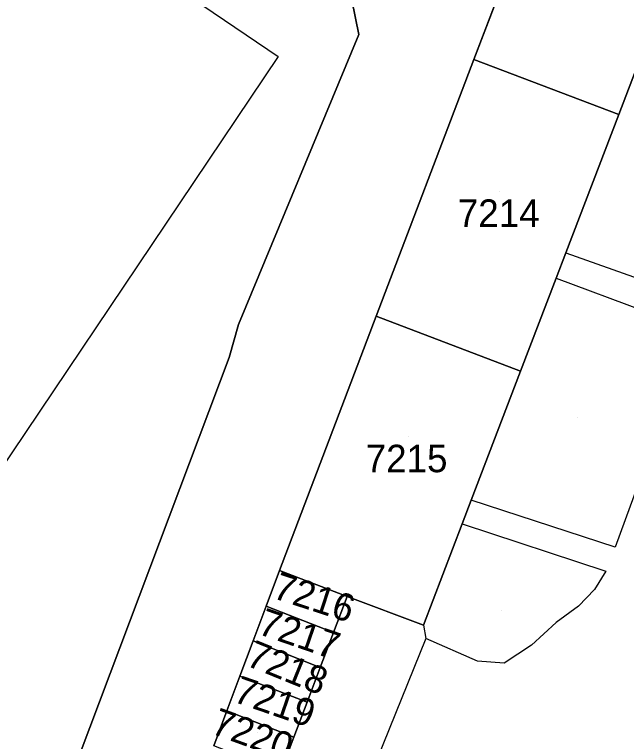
# Model space of a CAD drawing. Extents: x -266199 to -261993, y -1239047 to -1235108.
# Drawn here: x -263650.7 to -263606.2, y -1236545.7 to -1236492.8 of the extents above; entities that cross this region are included whole.
import ezdxf

# ---------------------------------------------------------------- set-up
doc = ezdxf.new("R2010")
doc.units = 0
for name, color, linetype in [('body_kn', 7, 'Continuous'), ('kladpar_druhypozemkov', 7, 'Continuous'), ('kladpar_hranice', 7, 'Continuous'), ('kladpar_parcelnecisla', 7, 'Continuous'), ('kladpar_plochy', 7, 'Continuous'), ('zappar_hrandruhpozemk', 7, 'Continuous')]:
    doc.layers.add(name, color=color, linetype=linetype)

msp = doc.modelspace()

# ---------------------------------------------------------------- linework, layer by layer
at = {"layer": 'body_kn'}
for p, q in [((-263625.65, -1236494.26), (-263625.65, -1236494.26)), ((-263631.52, -1236495.85), (-263631.52, -1236495.85)), ((-263631.52, -1236495.85), (-263631.52, -1236495.85)), ((-263617.27, -1236496.08), (-263617.27, -1236496.08)), ((-263617.27, -1236496.08), (-263617.27, -1236496.08)), ((-263606.72, -1236500.09), (-263606.72, -1236500.09)), ((-263606.72, -1236500.09), (-263606.72, -1236500.09)), ((-263610.57, -1236510.14), (-263610.57, -1236510.14)), ((-263610.57, -1236510.14), (-263610.57, -1236510.14)), ((-263611.28, -1236511.99), (-263611.28, -1236511.99)), ((-263611.28, -1236511.99), (-263611.28, -1236511.99)), ((-263624.38, -1236514.77), (-263624.38, -1236514.77)), ((-263624.38, -1236514.77), (-263624.38, -1236514.77)), ((-263634.41, -1236515.37), (-263634.41, -1236515.37)), ((-263635.09, -1236517.76), (-263635.09, -1236517.76)), ((-263613.87, -1236518.77), (-263613.87, -1236518.77)), ((-263613.87, -1236518.77), (-263613.87, -1236518.77)), ((-263617.46, -1236528.15), (-263617.46, -1236528.15)), ((-263618.12, -1236529.89), (-263618.12, -1236529.89)), ((-263618.12, -1236529.89), (-263618.12, -1236529.89)), ((-263607, -1236531.57), (-263607, -1236531.57)), ((-263631.43, -1236533.27), (-263631.43, -1236533.27)), ((-263631.43, -1236533.27), (-263631.43, -1236533.27)), ((-263607.67, -1236533.33), (-263607.67, -1236533.33)), ((-263626.49, -1236535.16), (-263626.49, -1236535.16)), ((-263608.5, -1236534.66), (-263608.5, -1236534.66)), ((-263632.4, -1236535.87), (-263632.4, -1236535.87)), ((-263632.4, -1236535.87), (-263632.4, -1236535.87)), ((-263609.66, -1236535.87), (-263609.66, -1236535.87)), ((-263620.94, -1236537.26), (-263620.94, -1236537.26)), ((-263620.94, -1236537.26), (-263620.94, -1236537.26)), ((-263611.28, -1236537.05), (-263611.28, -1236537.05)), ((-263627.48, -1236537.79), (-263627.48, -1236537.79)), ((-263620.77, -1236538.22), (-263620.77, -1236538.22)), ((-263620.77, -1236538.22), (-263620.77, -1236538.22)), ((-263633.34, -1236538.4), (-263633.34, -1236538.4)), ((-263633.34, -1236538.4), (-263633.34, -1236538.4)), ((-263613.07, -1236538.72), (-263613.07, -1236538.72)), ((-263617.02, -1236539.87), (-263617.02, -1236539.87)), ((-263628.45, -1236540.33), (-263628.45, -1236540.33)), ((-263615.08, -1236540.03), (-263615.08, -1236540.03)), ((-263634.3, -1236540.96), (-263634.3, -1236540.96)), ((-263634.3, -1236540.96), (-263634.3, -1236540.96)), ((-263629.41, -1236542.87), (-263629.41, -1236542.87)), ((-263635.24, -1236543.48), (-263635.24, -1236543.48)), ((-263635.24, -1236543.48), (-263635.24, -1236543.48)), ((-263630.37, -1236545.41), (-263630.37, -1236545.41))]:
    msp.add_line(p, q, dxfattribs=at)
at = {"layer": 'kladpar_druhypozemkov'}
for p, q in [((-263615.41, -1236505.66), (-263615.41, -1236505.66)), ((-263609.72, -1236522.16), (-263609.72, -1236522.16)), ((-263622.06, -1236523.52), (-263622.06, -1236523.52)), ((-263629.1, -1236534.51), (-263629.1, -1236534.51)), ((-263615.27, -1236536.16), (-263615.27, -1236536.16)), ((-263630.22, -1236537.23), (-263630.22, -1236537.23)), ((-263631.18, -1236539.86), (-263631.18, -1236539.86)), ((-263632.05, -1236542.42), (-263632.05, -1236542.42)), ((-263633.01, -1236545.05), (-263633.01, -1236545.05))]:
    msp.add_line(p, q, dxfattribs=at)
at = {"layer": 'kladpar_hranice'}
for p, q in [((-263624.38, -1236514.77), (-263617.27, -1236496.08)), ((-263606.72, -1236500.09), (-263617.27, -1236496.08)), ((-263617.27, -1236496.08), (-263606.72, -1236500.09)), ((-263631.43, -1236533.27), (-263624.38, -1236514.77)), ((-263613.87, -1236518.77), (-263624.38, -1236514.77)), ((-263624.38, -1236514.77), (-263613.87, -1236518.77))]:
    msp.add_line(p, q, dxfattribs=at)
for points in [[(-263745.77, -1236505), (-263720.79, -1236469.94), (-263655, -1236473.5), (-263653.26, -1236475.65), (-263656.07, -1236479.6), (-263655.84, -1236479.78), (-263652.12, -1236482.01), (-263651.91, -1236482.11), (-263647.44, -1236475.73), (-263645.5, -1236474.26), (-263626.44, -1236475.66), (-263626.33, -1236476.45), (-263628.77, -1236485.94), (-263628.88, -1236488.15), (-263626.15, -1236491.73), (-263625.65, -1236494.26), (-263634.41, -1236515.37), (-263635.09, -1236517.76), (-263650.28, -1236558.18), (-263636.73, -1236565.67), (-263652.65, -1236609.13)], [(-263652.65, -1236609.13), (-263636.73, -1236565.67), (-263650.28, -1236558.18), (-263635.09, -1236517.76), (-263634.41, -1236515.37), (-263625.65, -1236494.26), (-263626.15, -1236491.73), (-263628.88, -1236488.15), (-263628.77, -1236485.94), (-263626.33, -1236476.45), (-263626.44, -1236475.66), (-263645.5, -1236474.26)], [(-263611.39, -1236480.64), (-263617.27, -1236496.08), (-263624.38, -1236514.77), (-263631.43, -1236533.27), (-263632.4, -1236535.87), (-263633.34, -1236538.4), (-263634.3, -1236540.96), (-263635.24, -1236543.48), (-263636.19, -1236546.03)], [(-263631.33, -1236547.93), (-263630.37, -1236545.41), (-263629.41, -1236542.87), (-263628.45, -1236540.33), (-263627.48, -1236537.79), (-263626.49, -1236535.16), (-263620.94, -1236537.26), (-263618.12, -1236529.89), (-263617.46, -1236528.15), (-263613.87, -1236518.77), (-263611.28, -1236511.99), (-263610.57, -1236510.14), (-263606.72, -1236500.09), (-263604.37, -1236493.93), (-263603.7, -1236492.17), (-263600.8, -1236484.67), (-263611.39, -1236480.64)], [(-263617.27, -1236496.08), (-263611.39, -1236480.64), (-263600.8, -1236484.67), (-263603.7, -1236492.17), (-263604.37, -1236493.93), (-263606.72, -1236500.09)], [(-263606.72, -1236500.09), (-263610.57, -1236510.14), (-263611.28, -1236511.99), (-263613.87, -1236518.77)], [(-263613.87, -1236518.77), (-263617.46, -1236528.15), (-263618.12, -1236529.89), (-263620.94, -1236537.26), (-263626.49, -1236535.16), (-263631.43, -1236533.27)], [(-263632.4, -1236535.87), (-263631.43, -1236533.27), (-263626.49, -1236535.16), (-263627.48, -1236537.79), (-263632.4, -1236535.87)], [(-263633.34, -1236538.4), (-263632.4, -1236535.87), (-263627.48, -1236537.79), (-263628.45, -1236540.33), (-263633.34, -1236538.4)], [(-263634.3, -1236540.96), (-263633.34, -1236538.4), (-263628.45, -1236540.33), (-263629.41, -1236542.87), (-263634.3, -1236540.96)], [(-263635.24, -1236543.48), (-263634.3, -1236540.96), (-263629.41, -1236542.87), (-263630.37, -1236545.41), (-263635.24, -1236543.48)], [(-263636.19, -1236546.03), (-263635.24, -1236543.48), (-263630.37, -1236545.41), (-263631.33, -1236547.93), (-263636.19, -1236546.03)]]:
    msp.add_lwpolyline(points, dxfattribs=at)
at = {"layer": 'kladpar_plochy'}
for p, q in [((-263611.39, -1236480.64), (-263617.27, -1236496.08)), ((-263625.65, -1236494.26), (-263626.15, -1236491.73)), ((-263634.41, -1236515.37), (-263625.65, -1236494.26)), ((-263606.72, -1236500.09), (-263604.37, -1236493.93)), ((-263617.27, -1236496.08), (-263624.38, -1236514.77)), ((-263610.57, -1236510.14), (-263606.72, -1236500.09)), ((-263611.28, -1236511.99), (-263610.57, -1236510.14)), ((-263613.87, -1236518.77), (-263611.28, -1236511.99)), ((-263624.38, -1236514.77), (-263631.43, -1236533.27)), ((-263635.09, -1236517.76), (-263634.41, -1236515.37)), ((-263650.28, -1236558.18), (-263635.09, -1236517.76)), ((-263617.46, -1236528.15), (-263613.87, -1236518.77)), ((-263618.12, -1236529.89), (-263617.46, -1236528.15)), ((-263620.94, -1236537.26), (-263618.12, -1236529.89)), ((-263631.43, -1236533.27), (-263632.4, -1236535.87)), ((-263627.48, -1236537.79), (-263626.49, -1236535.16)), ((-263626.49, -1236535.16), (-263620.94, -1236537.26)), ((-263632.4, -1236535.87), (-263633.34, -1236538.4)), ((-263628.45, -1236540.33), (-263627.48, -1236537.79)), ((-263633.34, -1236538.4), (-263634.3, -1236540.96)), ((-263629.41, -1236542.87), (-263628.45, -1236540.33)), ((-263634.3, -1236540.96), (-263635.24, -1236543.48)), ((-263630.37, -1236545.41), (-263629.41, -1236542.87)), ((-263635.24, -1236543.48), (-263636.19, -1236546.03)), ((-263631.33, -1236547.93), (-263630.37, -1236545.41))]:
    msp.add_line(p, q, dxfattribs=at)
msp.add_lwpolyline([(-263745.77, -1236505), (-263720.79, -1236469.94), (-263655, -1236473.5), (-263653.26, -1236475.65), (-263656.07, -1236479.6), (-263655.84, -1236479.78), (-263652.12, -1236482.01), (-263651.91, -1236482.11), (-263647.44, -1236475.73), (-263645.5, -1236474.26), (-263626.44, -1236475.66), (-263626.33, -1236476.45), (-263628.77, -1236485.94), (-263628.88, -1236488.15), (-263626.15, -1236491.73), (-263625.65, -1236494.26), (-263634.41, -1236515.37), (-263635.09, -1236517.76), (-263650.28, -1236558.18), (-263636.73, -1236565.67), (-263652.65, -1236609.13)], dxfattribs=at)
for points in [[(-263617.27, -1236496.08), (-263611.39, -1236480.64), (-263600.8, -1236484.67), (-263603.7, -1236492.17), (-263604.37, -1236493.93), (-263606.72, -1236500.09)], [(-263624.38, -1236514.77), (-263617.27, -1236496.08), (-263606.72, -1236500.09), (-263610.57, -1236510.14), (-263611.28, -1236511.99), (-263613.87, -1236518.77)], [(-263631.43, -1236533.27), (-263624.38, -1236514.77), (-263613.87, -1236518.77), (-263617.46, -1236528.15), (-263618.12, -1236529.89), (-263620.94, -1236537.26), (-263626.49, -1236535.16)], [(-263632.4, -1236535.87), (-263631.43, -1236533.27), (-263626.49, -1236535.16), (-263627.48, -1236537.79)], [(-263633.34, -1236538.4), (-263632.4, -1236535.87), (-263627.48, -1236537.79), (-263628.45, -1236540.33)], [(-263634.3, -1236540.96), (-263633.34, -1236538.4), (-263628.45, -1236540.33), (-263629.41, -1236542.87)], [(-263635.24, -1236543.48), (-263634.3, -1236540.96), (-263629.41, -1236542.87), (-263630.37, -1236545.41)], [(-263636.19, -1236546.03), (-263635.24, -1236543.48), (-263630.37, -1236545.41), (-263631.33, -1236547.93)]]:
    msp.add_lwpolyline(points, close=True, dxfattribs=at)
at = {"layer": 'zappar_hrandruhpozemk'}
for p, q in [((-263631.52, -1236495.85), (-263660.65, -1236539.21)), ((-263610.57, -1236510.14), (-263600.55, -1236513.75)), ((-263611.28, -1236511.99), (-263601.21, -1236515.75)), ((-263601.21, -1236515.75), (-263607, -1236531.57)), ((-263607, -1236531.57), (-263617.46, -1236528.15)), ((-263620.94, -1236537.26), (-263620.77, -1236538.22)), ((-263620.77, -1236538.22), (-263627.88, -1236555.78)), ((-263613.07, -1236538.72), (-263615.08, -1236540.03))]:
    msp.add_line(p, q, dxfattribs=at)
for points in [[(-263660.65, -1236539.21), (-263679.97, -1236525.75), (-263651.12, -1236482.57), (-263631.52, -1236495.85)], [(-263618.12, -1236529.89), (-263607.67, -1236533.33), (-263608.5, -1236534.66), (-263609.66, -1236535.87), (-263611.28, -1236537.05), (-263613.07, -1236538.72)], [(-263615.08, -1236540.03), (-263617.02, -1236539.87), (-263620.77, -1236538.22)]]:
    msp.add_lwpolyline(points, dxfattribs=at)

# ---------------------------------------------------------------- texts
at = {"layer": 'kladpar_parcelnecisla'}
for s, p in [('7214', (-263618.44, -1236508.26)), ('7215', (-263625.145, -1236526.12))]:
    msp.add_text(s, height=2, dxfattribs=at).set_placement(p)
for s, rotation, p in [('7216', 342, (-263632.015, -1236535.254)), ('7217', 341, (-263633.091, -1236537.859)), ('7218', 338, (-263633.957, -1236540.152)), ('7219', 341, (-263634.886, -1236542.794)), ('7220', 340, (-263636.502, -1236545.112))]:
    msp.add_text(s, height=2, rotation=rotation, dxfattribs=at).set_placement(p)

doc.saveas('drawing.dxf')
